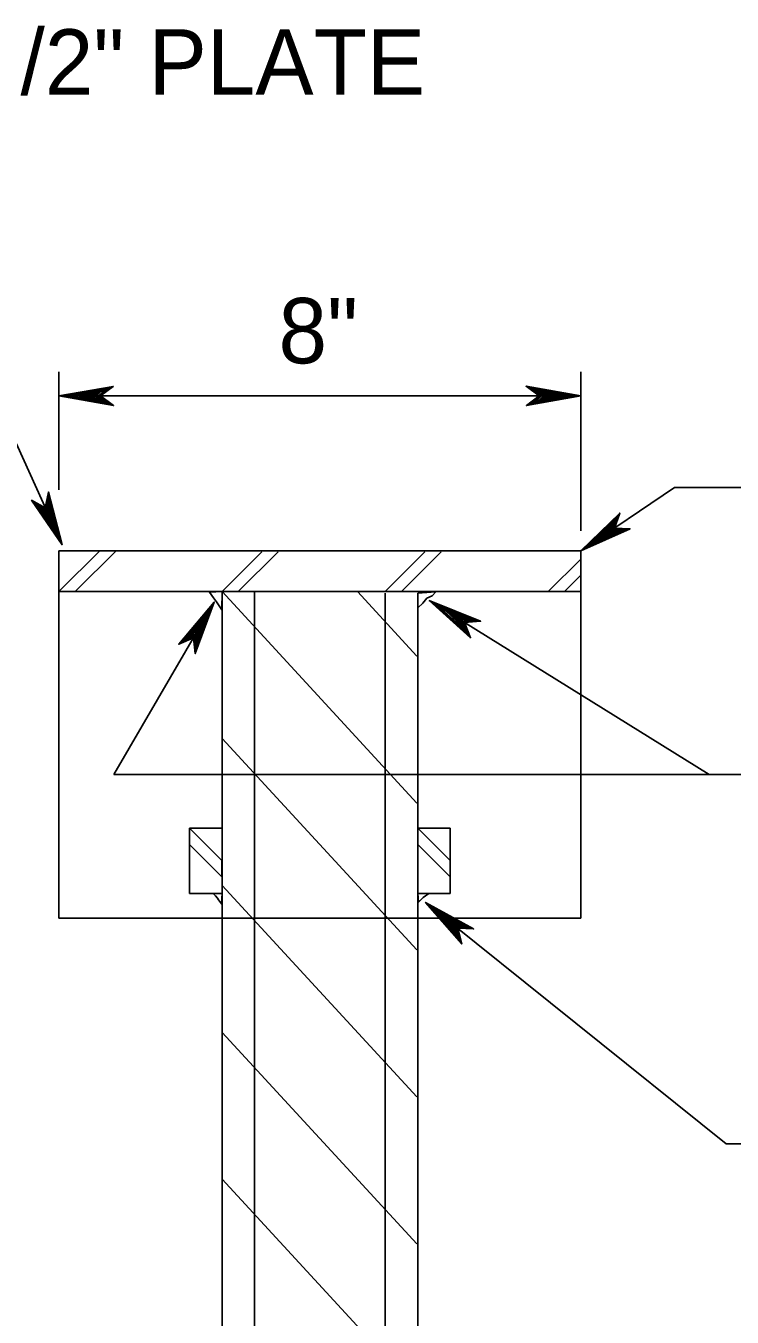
# Model space of a CAD drawing. Extents: x 499866 to 500993, y 499985 to 500645.
# Drawn here: x 500650.4 to 500693.7, y 500102.5 to 500181.6 of the extents above; entities that cross this region are included whole.
import ezdxf

# ---------------------------------------------------------------- set-up
doc = ezdxf.new("R2010")
doc.units = 0
for name, color, linetype in [('1', 7, 'Continuous'), ('24', 7, 'Continuous'), ('5', 7, 'Continuous'), ('60', 7, 'Continuous')]:
    doc.layers.add(name, color=color, linetype=linetype)

msp = doc.modelspace()

# ---------------------------------------------------------------- linework, layer by layer
at = {"layer": '1'}
for p, q in [((500662.444, 500146.946), (500674.385, 500134.005)), ((500670.742, 500146.946), (500674.385, 500142.998)), ((500662.444, 500137.952), (500674.385, 500125.011)), ((500662.444, 500128.959), (500674.385, 500116.019)), ((500662.444, 500119.966), (500674.385, 500107.025)), ((500662.444, 500110.972), (500674.385, 500098.032))]:
    msp.add_line(p, q, dxfattribs=at)
at = {"layer": '24'}
for points in [[(500652.451, 500158.922), (500655.801, 500158.33), (500655, 500158.922), (500655.783, 500159.505), (500652.451, 500158.922), (500652.673, 500158.928), (500655.707, 500158.374), (500654.938, 500158.929), (500655.648, 500159.459), (500652.793, 500158.938), (500652.905, 500158.922), (500655.504, 500158.46), (500654.921, 500158.929), (500655.52, 500159.384), (500652.956, 500158.922), (500653.067, 500158.938), (500655.339, 500158.528), (500654.897, 500158.922), (500655.348, 500159.33), (500653.391, 500158.939), (500653.58, 500158.938), (500655.17, 500158.613), (500654.861, 500158.912), (500655.194, 500159.245), (500653.614, 500158.922), (500653.792, 500158.911), (500654.988, 500158.707), (500654.758, 500158.939), (500655.008, 500159.168), (500653.957, 500158.922), (500654.125, 500158.905), (500654.844, 500158.768), (500654.725, 500158.929), (500654.921, 500159.108), (500654.213, 500158.922), (500654.681, 500158.81), (500654.614, 500158.938), (500654.819, 500159.067), (500654.331, 500158.939), (500654.638, 500158.862), (500654.509, 500158.963), (500654.657, 500159.023), (500654.51, 500158.929), (500654.587, 500158.912)], [(500684.427, 500158.922), (500681.076, 500159.514), (500681.877, 500158.922), (500681.094, 500158.339), (500684.427, 500158.922), (500684.204, 500158.916), (500681.17, 500159.47), (500681.939, 500158.915), (500681.229, 500158.385), (500684.084, 500158.906), (500683.972, 500158.922), (500681.374, 500159.384), (500681.957, 500158.915), (500681.357, 500158.46), (500683.921, 500158.922), (500683.81, 500158.906), (500681.538, 500159.316), (500681.98, 500158.922), (500681.529, 500158.513), (500683.487, 500158.905), (500683.298, 500158.906), (500681.707, 500159.231), (500682.016, 500158.931), (500681.683, 500158.598), (500683.264, 500158.922), (500683.085, 500158.932), (500681.889, 500159.137), (500682.119, 500158.905), (500681.87, 500158.676), (500682.921, 500158.922), (500682.752, 500158.939), (500682.033, 500159.076), (500682.152, 500158.915), (500681.956, 500158.736), (500682.664, 500158.922), (500682.196, 500159.033), (500682.264, 500158.906), (500682.058, 500158.777), (500682.547, 500158.905), (500682.239, 500158.982), (500682.368, 500158.881), (500682.22, 500158.821), (500682.367, 500158.915), (500682.29, 500158.931)], [(500652.643, 500149.817), (500651.811, 500153.036), (500651.609, 500152.084), (500650.773, 500152.544), (500652.643, 500149.817), (500652.547, 500150.012), (500651.81, 500152.935), (500651.628, 500152.026), (500650.869, 500152.442), (500652.49, 500150.115), (500652.459, 500150.22), (500651.816, 500152.719), (500651.635, 500152.01), (500650.988, 500152.359), (500652.439, 500150.266), (500652.379, 500150.358), (500651.822, 500152.545), (500651.651, 500151.992), (500651.105, 500152.228), (500652.247, 500150.646), (500652.171, 500150.814), (500651.815, 500152.361), (500651.674, 500151.964), (500651.243, 500152.125), (500652.171, 500150.851), (500652.108, 500151.014), (500651.805, 500152.161), (500651.692, 500151.862), (500651.387, 500151.991), (500652.032, 500151.156), (500651.979, 500151.313), (500651.81, 500152.007), (500651.714, 500151.837), (500651.476, 500151.938), (500651.929, 500151.384), (500651.838, 500151.846), (500651.751, 500151.734), (500651.554, 500151.864), (500651.865, 500151.482), (500651.809, 500151.786), (500651.772, 500151.631), (500651.658, 500151.738), (500651.801, 500151.645), (500651.785, 500151.72)], [(500684.427, 500149.444), (500686.814, 500151.758), (500686.49, 500150.84), (500687.443, 500150.798), (500684.427, 500149.444), (500684.61, 500149.56), (500686.762, 500151.671), (500686.444, 500150.8), (500687.308, 500150.76), (500684.713, 500149.617), (500684.794, 500149.692), (500686.644, 500151.49), (500686.429, 500150.791), (500687.164, 500150.751), (500684.835, 500149.721), (500684.934, 500149.768), (500686.549, 500151.344), (500686.406, 500150.784), (500686.995, 500150.7), (500685.197, 500149.945), (500685.349, 500150.049), (500686.459, 500151.183), (500686.372, 500150.771), (500686.824, 500150.684), (500685.367, 500150.08), (500685.507, 500150.187), (500686.363, 500151.008), (500686.303, 500150.694), (500686.631, 500150.645), (500685.646, 500150.268), (500685.773, 500150.375), (500686.279, 500150.879), (500686.272, 500150.684), (500686.528, 500150.646), (500685.853, 500150.409), (500686.171, 500150.756), (500686.186, 500150.615), (500686.423, 500150.623), (500685.958, 500150.46), (500686.164, 500150.69), (500686.115, 500150.538), (500686.268, 500150.57), (500686.097, 500150.566), (500686.15, 500150.621)], [(500675.145, 500146.397), (500677.677, 500144.125), (500677.31, 500145.051), (500678.283, 500145.132), (500675.145, 500146.397), (500675.337, 500146.284), (500677.621, 500144.212), (500677.261, 500145.09), (500678.144, 500145.165), (500675.444, 500146.23), (500675.53, 500146.157), (500677.493, 500144.393), (500677.246, 500145.098), (500677.995, 500145.168), (500675.573, 500146.13), (500675.677, 500146.085), (500677.39, 500144.537), (500677.222, 500145.105), (500677.821, 500145.214), (500675.952, 500145.915), (500676.112, 500145.815), (500677.291, 500144.698), (500677.186, 500145.116), (500677.645, 500145.223), (500676.132, 500145.783), (500676.279, 500145.679), (500677.186, 500144.874), (500677.113, 500145.193), (500677.446, 500145.256), (500676.424, 500145.602), (500676.558, 500145.498), (500677.095, 500145.002), (500677.08, 500145.202), (500677.341, 500145.251), (500676.641, 500145.466), (500676.98, 500145.124), (500676.99, 500145.269), (500677.233, 500145.269), (500676.75, 500145.419), (500676.971, 500145.191), (500676.914, 500145.345), (500677.072, 500145.318), (500676.898, 500145.316), (500676.954, 500145.261)], [(500674.912, 500127.92), (500677.137, 500125.382), (500676.885, 500126.337), (500677.853, 500126.302), (500674.912, 500127.92), (500675.088, 500127.787), (500677.092, 500125.474), (500676.841, 500126.382), (500677.72, 500126.35), (500675.188, 500127.72), (500675.263, 500127.638), (500676.988, 500125.667), (500676.828, 500126.392), (500677.574, 500126.371), (500675.303, 500127.606), (500675.399, 500127.55), (500676.903, 500125.822), (500676.805, 500126.401), (500677.407, 500126.437), (500675.65, 500127.35), (500675.796, 500127.232), (500676.825, 500125.992), (500676.771, 500126.416), (500677.236, 500126.467), (500675.812, 500127.198), (500675.944, 500127.079), (500676.742, 500126.178), (500676.708, 500126.501), (500677.044, 500126.523), (500676.078, 500126.985), (500676.198, 500126.867), (500676.668, 500126.315), (500676.677, 500126.513), (500676.94, 500126.53), (500676.275, 500126.826), (500676.569, 500126.449), (500676.596, 500126.59), (500676.835, 500126.562), (500676.378, 500126.766), (500676.568, 500126.515), (500676.531, 500126.674), (500676.683, 500126.629), (500676.51, 500126.647), (500676.56, 500126.586)], [(500674.912, 500127.92), (500677.137, 500125.382), (500676.885, 500126.337), (500677.853, 500126.302), (500674.912, 500127.92), (500675.088, 500127.787), (500677.092, 500125.474), (500676.841, 500126.382), (500677.72, 500126.35), (500675.188, 500127.72), (500675.263, 500127.638), (500676.988, 500125.667), (500676.828, 500126.392), (500677.574, 500126.371), (500675.303, 500127.606), (500675.399, 500127.55), (500676.903, 500125.822), (500676.805, 500126.401), (500677.407, 500126.437), (500675.65, 500127.35), (500675.796, 500127.232), (500676.825, 500125.992), (500676.771, 500126.416), (500677.236, 500126.467), (500675.812, 500127.198), (500675.944, 500127.079), (500676.742, 500126.178), (500676.708, 500126.501), (500677.044, 500126.523), (500676.078, 500126.985), (500676.198, 500126.867), (500676.668, 500126.315), (500676.677, 500126.513), (500676.94, 500126.53), (500676.275, 500126.826), (500676.569, 500126.449), (500676.596, 500126.59), (500676.835, 500126.562), (500676.378, 500126.766), (500676.568, 500126.515), (500676.531, 500126.674), (500676.683, 500126.629), (500676.51, 500126.647), (500676.56, 500126.586)]]:
    msp.add_lwpolyline(points, dxfattribs=at)
at = {"layer": '5'}
for p, q in [((500639.165, 500179.37), (500652.643, 500149.817)), ((500652.451, 500153.169), (500652.451, 500160.405)), ((500684.427, 500150.665), (500684.427, 500160.405)), ((500652.451, 500158.922), (500684.427, 500158.922)), ((500652.451, 500146.946), (500654.972, 500149.467)), ((500652.451, 500149.444), (500652.451, 500126.95)), ((500652.451, 500149.444), (500684.427, 500149.444)), ((500653.45, 500146.946), (500655.972, 500149.467)), ((500662.444, 500146.946), (500664.886, 500149.388)), ((500663.443, 500146.946), (500665.875, 500149.378)), ((500672.436, 500146.946), (500674.879, 500149.388)), ((500673.435, 500146.946), (500675.867, 500149.378)), ((500684.427, 500149.444), (500684.427, 500126.95)), ((500682.428, 500146.946), (500684.4, 500148.917)), ((500683.427, 500146.946), (500684.438, 500147.956)), ((500652.451, 500146.946), (500684.427, 500146.946)), ((500662.444, 500146.946), (500662.444, 500052.017)), ((500664.442, 500146.946), (500664.442, 500052.017)), ((500672.436, 500146.86), (500672.436, 500052.017)), ((500674.434, 500146.86), (500674.434, 500052.017)), ((500655.808, 500135.744), (500661.973, 500146.302)), ((500692.281, 500135.744), (500675.145, 500146.397)), ((500692.281, 500135.744), (500655.808, 500135.744)), ((500713.682, 500135.744), (500692.281, 500135.744)), ((500660.445, 500132.456), (500660.445, 500128.459)), ((500660.445, 500132.456), (500662.444, 500132.456)), ((500674.434, 500132.456), (500676.433, 500132.456)), ((500676.433, 500132.456), (500676.433, 500128.459)), ((500660.445, 500128.459), (500662.444, 500128.459)), ((500674.434, 500128.459), (500676.433, 500128.459)), ((500652.451, 500126.95), (500662.444, 500126.95)), ((500662.444, 500126.95), (500674.434, 500126.95)), ((500674.434, 500126.95), (500684.427, 500126.95))]:
    msp.add_line(p, q, dxfattribs=at)
for points in [[(500695.156, 500153.324), (500690.16, 500153.324), (500684.427, 500149.444)], [(500661.973, 500146.302), (500659.79, 500143.728), (500660.698, 500144.118), (500660.806, 500143.155), (500661.973, 500146.302), (500661.867, 500146.108), (500659.875, 500143.787), (500660.736, 500144.167), (500660.834, 500143.294), (500661.816, 500146.001), (500661.746, 500145.913), (500660.05, 500143.917), (500660.744, 500144.183), (500660.834, 500143.442), (500661.72, 500145.869), (500661.679, 500145.766), (500660.192, 500144.025), (500660.749, 500144.206), (500660.874, 500143.615), (500661.518, 500145.488), (500661.423, 500145.326), (500660.348, 500144.127), (500660.76, 500144.242), (500660.878, 500143.79), (500661.392, 500145.306), (500661.293, 500145.158), (500660.519, 500144.236), (500660.834, 500144.317), (500660.905, 500143.988), (500661.22, 500145.012), (500661.121, 500144.876), (500660.644, 500144.329), (500660.842, 500144.35), (500660.897, 500144.093), (500661.092, 500144.793), (500660.762, 500144.447), (500660.906, 500144.441), (500660.913, 500144.2), (500661.047, 500144.683), (500660.828, 500144.458), (500660.979, 500144.518), (500660.957, 500144.361), (500660.949, 500144.534), (500660.897, 500144.476)], [(500718.354, 500113.137), (500693.336, 500113.137), (500674.912, 500127.92)]]:
    msp.add_lwpolyline(points, dxfattribs=at)
at = {"layer": '60'}
for points in [[(500662.444, 500146.946), (500661.677, 500146.911), (500661.93, 500146.572), (500662.1, 500146.318), (500662.439, 500145.838)], [(500674.434, 500146.86), (500674.437, 500145.951), (500674.747, 500146.233), (500675.001, 500146.544), (500675.312, 500146.685), (500675.537, 500146.939)], [(500660.445, 500132.456), (500660.445, 500131.457), (500662.432, 500129.483), (500662.432, 500130.482)], [(500674.434, 500132.456), (500674.434, 500131.457), (500676.421, 500129.483), (500676.421, 500130.482)], [(500662.444, 500128.459), (500661.916, 500128.44), (500662.043, 500128.313), (500662.171, 500128.172), (500662.227, 500128.088), (500662.41, 500127.833)], [(500674.434, 500128.459), (500674.479, 500127.939), (500674.761, 500128.221), (500675.114, 500128.462)]]:
    msp.add_lwpolyline(points, close=True, dxfattribs=at)

# ---------------------------------------------------------------- texts
at = {"layer": '5'}
for s, p in [('1/2" PLATE', (500647.125, 500177.37)), ('8"', (500665.906, 500160.922))]:
    msp.add_text(s, height=4, dxfattribs=at).set_placement(p)

doc.saveas('drawing.dxf')
